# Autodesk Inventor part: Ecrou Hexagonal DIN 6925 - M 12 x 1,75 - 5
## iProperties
Created: 2002-09
Part Number: Ecrou Hexagonal DIN 6925 - M 12 x 1,75 - 5
Material: Par défaut
Catalog Web Link: www.traceparts.com
Description: Ecrou Hexagonal DIN 6925 - M 12 x 1,75 - 5
Document SubType Name: Modélisation
Designer: Maison
Control State: 0
Master: False
Checked Out: False
Shininess: 20.0
Length Units: 11269
Angle Units: 11279
Time Units: 11290
Mass Units: 11283
Length Display Precision: 3
Angle Display Precision: 2
Density: 0.0
Volumn: 0.0
Area: 0.0
PropertySet Name: Model Information
Author: Maison
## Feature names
1. Base1
